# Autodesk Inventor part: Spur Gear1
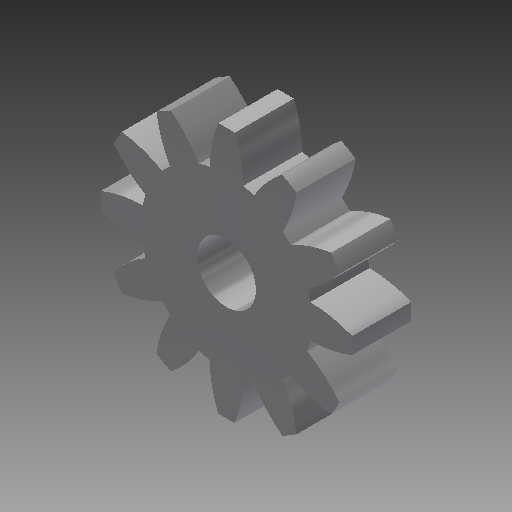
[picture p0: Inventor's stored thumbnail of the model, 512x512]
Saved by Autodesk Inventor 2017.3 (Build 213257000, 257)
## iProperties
Created: 2020-03
Part Number: Spur Gear1
Material: Steel
Document SubType Name: Modeling
Designer: Tim_G
Categories: <?xml version="1.0" encoding="UTF-16"?> <MemberInstance><Categories><FamilyTemplate><FamilyTemplateParameter ValueType="xs:double" Id="1" ObjectReferenceKey="da
Density: 1 g/cm^3
Appearance: Steel
CustomPartVersion: 1
Author: Tim_G
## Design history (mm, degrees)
sketch "Sketch1"
  geometry: C1 r 10.661 at (0, 0)
  constraints: 1 centre point
  dimensions: "d0" = 21.3211 diameter of C1 (= da_da)
extrude "Extrusion1" new body sketch "Sketch1" distance "d1" = 5 (= da_b); taper "d2" = 0 deg
workplane "Work Plane2"
sketch "Sketch2"
  geometry: C1 r 10.661 at (0, 0) reference; C2 r 9.138 at (0, 0)
  constraints: 1 centre point, 1 coincident
  dimensions: "d3" = 18.27523 diameter of C2 (= da_dw)
feature "Pitch Diameter" sketch "Sketch2" dims "d4" = 10, "d5" = 0
workplane "Work Plane8"
workplane "Work Plane9"
feature "Spur Gear" dims "da_b" = 5, "da_d" = 18.27523, "da_aw" = 27.41284, "da_da" = 21.3211, "da_df" = 14.46789, "da_dw" = 18.27523, angle "da_beta" = 0 deg, "da_lefttooth" = 0, "da_righttooth" = 0
sketch "Sketch3"
  geometry: C1 r 2.5 at (0, 0); 1 further point
  constraints: 1 centre point, 1 coincident
  dimensions: "d49" = 5 diameter of C1
extrude "Extrusion2" cut sketch "Sketch3" distance "d50" = 5; taper "d51" = 0 deg
body "Solid1"
body "Srf1"
other parameters: "d16" = 27.41284 (= da_aw), "d17" = 0, "d34" = 15 deg (computed from da_z), "d39" = 0, "d41" = 0, "d43" = 27.41284 (= da_aw), "d46" = 27.41284 (= da_aw), "d47" = 0, "d48" = 0
